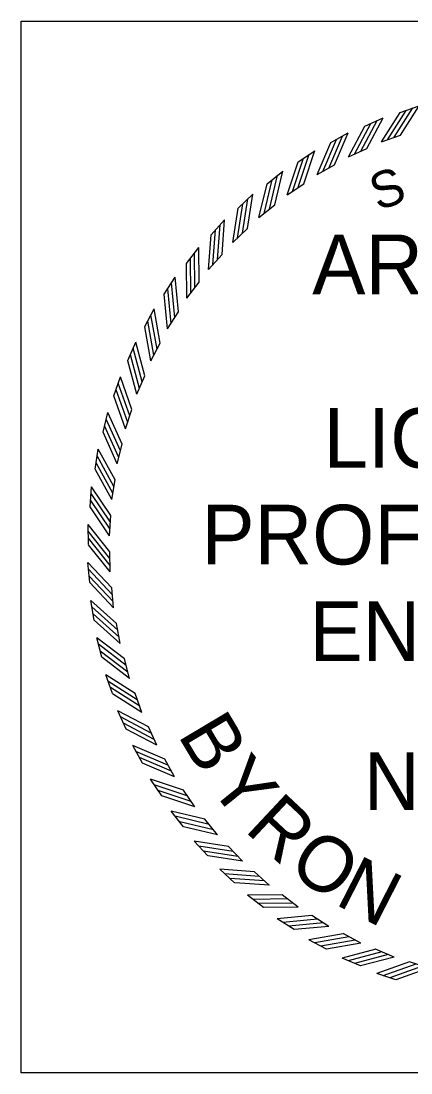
# Model space of a CAD drawing. Extents: x 0 to 1228740, y 0 to 152440.
# Drawn here: x 33.615 to 34.632, y 23.01 to 25.752 of the extents above; entities that cross this region are included whole.
import ezdxf

# ---------------------------------------------------------------- set-up
doc = ezdxf.new("R2010")
doc.units = 0
doc.layers.add('R_No Plot', color=7, linetype='Continuous')
doc.layers.add('STAMP', color=7, linetype='Continuous')

msp = doc.modelspace()

# ---------------------------------------------------------------- linework, layer by layer
at = {"layer": 'R_No Plot'}
msp.add_lwpolyline([(33.6152, 25.7521), (36.3569, 25.7521), (36.3569, 23.0104), (33.6152, 23.0104)], close=True, dxfattribs=at)
at = {"layer": 'STAMP'}
for p, q in [((34.6037, 25.5136), (34.6531, 25.5311)), ((34.5115, 25.4782), (34.5593, 25.4997)), ((34.4226, 25.4353), (34.4684, 25.4606)), ((34.5549, 25.4372), (34.6044, 25.4547)), ((34.4692, 25.398), (34.5171, 25.4196)), ((34.3375, 25.3851), (34.3811, 25.4142)), ((34.387, 25.3519), (34.4329, 25.3773)), ((34.2568, 25.3282), (34.2978, 25.3607)), ((34.3089, 25.2991), (34.3526, 25.3282)), ((34.1811, 25.2647), (34.2193, 25.3005)), ((34.2354, 25.24), (34.2765, 25.2727)), ((34.1109, 25.1952), (34.146, 25.2341)), ((34.167, 25.1751), (34.2054, 25.211)), ((34.0466, 25.1202), (34.0784, 25.1618)), ((34.1043, 25.1048), (34.1395, 25.1437)), ((33.9888, 25.0401), (34.0171, 25.0842)), ((34.0476, 25.0295), (34.0794, 25.0712)), ((33.9378, 24.9555), (33.9623, 25.0018)), ((33.9972, 24.9498), (34.0256, 24.994)), ((33.894, 24.8669), (33.9146, 24.9151)), ((33.9537, 24.8662), (33.9782, 24.9126)), ((33.8576, 24.7751), (33.8742, 24.8248)), ((33.9171, 24.7793), (33.9378, 24.8275)), ((33.829, 24.6806), (33.8413, 24.7315)), ((33.8879, 24.6896), (33.9045, 24.7395)), ((33.8662, 24.5979), (33.8786, 24.6489)), ((33.8082, 24.584), (33.8163, 24.6358)), ((33.7955, 24.486), (33.7993, 24.5383)), ((33.8522, 24.5047), (33.8603, 24.5566)), ((33.8458, 24.4106), (33.8497, 24.463)), ((33.7909, 24.3874), (33.7904, 24.4398)), ((33.8473, 24.3164), (33.8468, 24.3689)), ((33.7945, 24.2886), (33.7897, 24.3408)), ((33.8566, 24.2226), (33.8517, 24.2749)), ((33.8062, 24.1906), (33.7971, 24.2422)), ((33.8735, 24.1298), (33.8644, 24.1815)), ((33.826, 24.0938), (33.8126, 24.1445)), ((33.8981, 24.0388), (33.8847, 24.0896)), ((33.8537, 23.999), (33.8362, 24.0484)), ((33.9301, 23.9501), (33.9126, 23.9997)), ((33.8891, 23.9068), (33.8676, 23.9546)), ((33.9693, 23.8644), (33.9477, 23.9123)), ((33.932, 23.8178), (33.9067, 23.8637)), ((34.0154, 23.7822), (33.99, 23.8282)), ((33.9822, 23.7327), (33.9531, 23.7763)), ((34.0682, 23.7041), (34.0391, 23.7478)), ((34.0391, 23.652), (34.0066, 23.6931)), ((34.1273, 23.6306), (34.0946, 23.6718)), ((34.1026, 23.5763), (34.0668, 23.6145)), ((34.1922, 23.5623), (34.1563, 23.6006)), ((34.1721, 23.5061), (34.1332, 23.5412)), ((34.2625, 23.4995), (34.2236, 23.5347)), ((34.2471, 23.4419), (34.2055, 23.4737)), ((34.3378, 23.4428), (34.2961, 23.4747)), ((34.4175, 23.3925), (34.3733, 23.4208)), ((34.3272, 23.3841), (34.2831, 23.4123)), ((34.5011, 23.3489), (34.4547, 23.3735)), ((34.4118, 23.3331), (34.3655, 23.3576)), ((34.588, 23.3124), (34.5397, 23.333)), ((34.5004, 23.2892), (34.4522, 23.3098)), ((34.6777, 23.2832), (34.6278, 23.2998)), ((34.5922, 23.2528), (34.5425, 23.2694))]:
    msp.add_line(p, q, dxfattribs=at)
for points in [[(34.5878, 25.4491), (34.6367, 25.5255)], [(34.6044, 25.4547), (34.6532, 25.5312)], [(34.517, 25.4196), (34.5594, 25.4997)], [(34.5549, 25.4372), (34.6037, 25.5136)], [(34.5708, 25.4426), (34.6196, 25.519)], [(34.4691, 25.3979), (34.5115, 25.4781)], [(34.4846, 25.4047), (34.5269, 25.4849)], [(34.501, 25.4126), (34.5434, 25.4927)], [(34.4018, 25.3598), (34.4374, 25.4432)], [(34.4175, 25.369), (34.4531, 25.4524)], [(34.4329, 25.3773), (34.4684, 25.4607)], [(34.387, 25.3518), (34.4225, 25.4352)], [(34.323, 25.3082), (34.3515, 25.3943)], [(34.3379, 25.3187), (34.3665, 25.4047)], [(34.3525, 25.3282), (34.3811, 25.4143)], [(34.3089, 25.299), (34.3374, 25.3851)], [(34.2487, 25.2503), (34.2701, 25.3384)], [(34.2627, 25.2619), (34.2841, 25.3501)], [(34.2765, 25.2727), (34.2978, 25.3608)], [(34.2354, 25.2399), (34.2567, 25.3281)], [(34.1924, 25.1992), (34.2065, 25.2888)], [(34.2053, 25.211), (34.2193, 25.3006)], [(34.167, 25.175), (34.181, 25.2646)], [(34.1794, 25.1864), (34.1935, 25.276)], [(34.1394, 25.1437), (34.146, 25.2341)], [(34.1157, 25.1171), (34.1223, 25.2075)], [(34.1276, 25.1309), (34.1342, 25.2213)], [(34.1043, 25.1047), (34.1108, 25.1951)], [(34.0686, 25.0574), (34.0677, 25.1481)], [(34.0794, 25.0712), (34.0784, 25.1619)], [(34.0476, 25.0294), (34.0466, 25.1201)], [(34.0579, 25.0427), (34.057, 25.1334)], [(34.0159, 24.9793), (34.0075, 25.0696)], [(34.0255, 24.994), (34.0171, 25.0842)], [(33.9972, 24.9497), (33.9888, 25.04)], [(34.0065, 24.9638), (33.9981, 25.0541)], [(33.9699, 24.8972), (33.954, 24.9865)], [(33.9782, 24.9126), (33.9623, 25.0018)], [(33.9537, 24.8661), (33.9378, 24.9554)], [(33.9617, 24.8809), (33.9459, 24.9702)], [(33.9307, 24.8115), (33.9076, 24.8992)], [(33.9377, 24.8275), (33.9146, 24.9152)], [(33.9239, 24.7946), (33.9008, 24.8823)], [(33.9172, 24.7792), (33.894, 24.8668)], [(33.9045, 24.7394), (33.8742, 24.8249)], [(33.8934, 24.7055), (33.8631, 24.791)], [(33.8988, 24.7229), (33.8685, 24.8084)], [(33.888, 24.6896), (33.8576, 24.775)], [(33.8786, 24.6489), (33.8413, 24.7315)], [(33.8743, 24.632), (33.837, 24.7146)], [(33.8662, 24.5978), (33.829, 24.6805)], [(33.8704, 24.6142), (33.8331, 24.6968)], [(33.8603, 24.5565), (33.8163, 24.6358)], [(33.855, 24.5212), (33.811, 24.6005)], [(33.8574, 24.5393), (33.8134, 24.6186)], [(33.8522, 24.5046), (33.8082, 24.5839)], [(33.8496, 24.4629), (33.7993, 24.5383)], [(33.8482, 24.4456), (33.7978, 24.5209)], [(33.8459, 24.4106), (33.7955, 24.486)], [(33.8473, 24.4274), (33.7969, 24.5028)], [(33.8468, 24.3688), (33.7904, 24.4398)], [(33.8468, 24.3514), (33.7904, 24.4224)], [(33.8474, 24.3332), (33.7909, 24.4042)], [(33.8474, 24.3163), (33.7909, 24.3873)], [(33.8517, 24.2748), (33.7896, 24.3409)], [(33.8531, 24.2574), (33.7911, 24.3235)], [(33.8552, 24.2393), (33.7931, 24.3054)], [(33.8566, 24.2225), (33.7945, 24.2886)], [(33.8644, 24.1815), (33.797, 24.2422)], [(33.8672, 24.1643), (33.7999, 24.225)], [(33.8708, 24.1464), (33.8035, 24.2071)], [(33.8736, 24.1298), (33.8062, 24.1905)], [(33.8847, 24.0895), (33.8126, 24.1445)], [(33.889, 24.0726), (33.8169, 24.1276)], [(33.894, 24.0551), (33.8219, 24.1101)], [(33.8981, 24.0388), (33.826, 24.0937)], [(33.9125, 23.9996), (33.8361, 24.0484)], [(33.9182, 23.9831), (33.8418, 24.0319)], [(33.9247, 23.966), (33.8483, 24.0149)], [(33.9301, 23.9501), (33.8537, 23.9989)], [(33.9477, 23.9122), (33.8676, 23.9546)], [(33.9547, 23.8963), (33.8746, 23.9386)], [(33.9626, 23.8798), (33.8824, 23.9222)], [(33.9694, 23.8644), (33.8892, 23.9067)], [(33.99, 23.8281), (33.9066, 23.8637)], [(33.9983, 23.8127), (33.9149, 23.8483)], [(34.0075, 23.797), (33.9241, 23.8326)], [(34.0155, 23.7822), (33.9321, 23.8178)], [(34.0391, 23.7477), (33.953, 23.7763)], [(34.0486, 23.7331), (33.9626, 23.7617)], [(34.0591, 23.7182), (33.973, 23.7468)], [(34.0683, 23.7041), (33.9822, 23.7326)], [(34.0946, 23.6717), (34.0065, 23.6931)], [(34.1054, 23.6579), (34.0172, 23.6793)], [(34.117, 23.6439), (34.0289, 23.6653)], [(34.1274, 23.6306), (34.0392, 23.652)], [(34.1563, 23.6005), (34.0667, 23.6145)], [(34.1681, 23.5877), (34.0785, 23.6017)], [(34.1808, 23.5747), (34.0913, 23.5887)], [(34.1923, 23.5623), (34.1027, 23.5763)], [(34.2236, 23.5347), (34.1332, 23.5412)], [(34.2364, 23.5228), (34.146, 23.5294)], [(34.2502, 23.5109), (34.1598, 23.5175)], [(34.2626, 23.4995), (34.1722, 23.5061)], [(34.2961, 23.4746), (34.2054, 23.4737)], [(34.3099, 23.4639), (34.2192, 23.4629)], [(34.3246, 23.4531), (34.2339, 23.4522)], [(34.3379, 23.4428), (34.2472, 23.4419)], [(34.3733, 23.4207), (34.2831, 23.4123)], [(34.3879, 23.4112), (34.2977, 23.4028)], [(34.4035, 23.4017), (34.3132, 23.3933)], [(34.4176, 23.3925), (34.3273, 23.3841)], [(34.4547, 23.3734), (34.3655, 23.3576)], [(34.4701, 23.3651), (34.3808, 23.3493)], [(34.4864, 23.3569), (34.3971, 23.3411)], [(34.5012, 23.3489), (34.4119, 23.3331)], [(34.5398, 23.333), (34.4521, 23.3098)], [(34.5558, 23.326), (34.4681, 23.3028)], [(34.5727, 23.3192), (34.485, 23.296)], [(34.5881, 23.3124), (34.5005, 23.2892)], [(34.6279, 23.2997), (34.5424, 23.2694)], [(34.6444, 23.294), (34.5589, 23.2637)], [(34.6618, 23.2887), (34.5763, 23.2583)], [(34.6777, 23.2832), (34.5923, 23.2529)]]:
    msp.add_lwpolyline(points, dxfattribs=at)

# ---------------------------------------------------------------- texts
for s, height, rotation, p in [('S', 0.0953, 19.7726, (34.5457, 25.2567)), ('B', 0.1448, 300.7985, (34.0221, 23.8918)), ('Y', 0.1448, 308.8241, (34.0999, 23.7613)), ('R', 0.1448, 316.8497, (34.1952, 23.6429)), ('O', 0.1448, 324.8753, (34.306, 23.539)), ('N', 0.1448, 332.9009, (34.4303, 23.4516))]:
    msp.add_text(s, height=height, rotation=rotation, dxfattribs=at).set_placement(p)
for s, height, p in [('ARKANSAS', 0.15559, (34.3744, 25.0399)), ('LICENSED', 0.15559, (34.404, 24.5876)), ('PROFESSIONAL', 0.155594, (34.0854, 24.3357)), ('ENGINEER', 0.15559, (34.367, 24.0838)), ('No.13640', 0.15004, (34.5092, 23.6959))]:
    msp.add_text(s, height=height, dxfattribs=at).set_placement(p)

doc.saveas('drawing.dxf')
